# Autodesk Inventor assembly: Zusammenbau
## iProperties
Created: 2006-07
Part Number: Zusammenbau
Document SubType Name: Assembly
Designer: I.Baliuc
Description: Hochstromlasttrenner HSLT 18 KA
Cost Center: 144,516 kg
Authority: 21929557 mm^3
Mass: 146982 g
Surface Area: 58665.6 cm^2
Volume: 21929.6 cm^3
Density: 6.70244 g/cm^3
Comments: 18 KA 3-polig mit Motorantrieb
Title: Hochstromlasttrenner
Company: Mayer & Müller AG Schaltgeräte
Zweck: High Current Breaaker HSLT 18 KA
SaveDate: 2006-11-06
SaveTime: 23:22
TotalMass: 144,516 kg
TotalVolume: 21929557 mm^3
dX*dY*dZ: 705mm x 970mm x 602mm
Flaeche: 5866561 mm²
Volumen: 21929630 mm³
Author: T.Messerschmitt
Revision Number: 309022
